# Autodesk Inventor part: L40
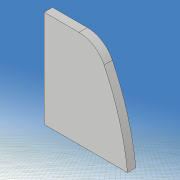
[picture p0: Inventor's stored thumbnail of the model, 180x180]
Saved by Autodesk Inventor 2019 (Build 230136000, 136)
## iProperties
Created: 2021-05
Part Number: L40
Material: 一般
Document SubType Name: Modeling
Designer: kikut
Density: 1 g/cm^3
Appearance: 既定
Mass: 0.00934248 g
Surface Area: 0.426451 cm^2
Volume: 0.00934248 cm^3
Author: kikut
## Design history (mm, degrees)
sketch "スケッチ1"
  geometry: L1 (80, 60)-(-80, 60); L2 (-80, 60)-(-80, -60); L3 (-80, -60)-(80, -60); L4 (80, -60)-(80, 60); L5 (80, 60)-(-80, -60); L6 (-80, 60)-(80, -60); 1 further point
  constraints: 12 end point, 2 midpoint, 2 parallel, 1 horizontal, 1 perpendicular
  dimensions: "d0" = 160 distance of L2.end L3.end; "d1" = 120 distance of L1.end L2.end
extrude "押し出し1" new body sketch "スケッチ1" stored distance "d2" = 0.6; taper "d3" = 0 deg
sketch "スケッチ2"
  geometry: L1 (-140, 0)-(140, 0) reference; L2 (0, -54)-(20, -30); L3 (0, 54)-(20, 30); L4 (0, -3)-(6.514, -3); L5 (6.514, -3)-(16, -6); L6 (16, -6)-(24, -3); L7 (24, -3)-(33.716, -3); L8 (0, 3)-(6.514, 3); L9 (6.514, 3)-(16, 6); L10 (16, 6)-(24, 3); L11 (24, 3)-(33.716, 3); L12 (0, -98)-(0, 98) reference; L13 (-100, -70)-(100, -70); L14 (100, -70)-(100, 70); L15 (100, 70)-(-100, 70); L16 (-100, 70)-(-100, -70); L17 (-100, -70)-(100, 70); L18 (100, -70)-(-100, 70); A1 r 60 centre (54.312, 28.5) between (0, 54) and (0, 3); A2 r 60 centre (54.312, -28.5) between (0, -3) and (0, -54); A3 r 18.111 centre (18, -12) between (20, -30) and (33.716, -3); A4 r 18.111 centre (18, 12) between (33.716, 3) and (20, 30); 1 further point
  constraints: 32 end point, 8 point on circle, 8 symmetric about line, 4 centre point, 3 horizontal, 2 collinear, 2 midpoint, 2 parallel, 1 perpendicular
  dimensions: "d5" = 60 radius of A1; "d6" = 6 distance of L8.start L4.start; "d7" = 108 distance of L3.start L2.start; "d8" = 0 horizontal distance of L3.start L8.start; "d9" = 60 distance of L3.end L2.end; "d10" = 0 horizontal distance of point (0, 0) L3.start; "d11" = 20 horizontal distance of L3.start L3.end; "d12" = 24 distance of A4.centre A3.centre; "d13" = 6 distance of L11.end L7.end; "d14" = 12 distance of L9.end L5.end; "d15" = 16 distance from line of L12 L5.end; "d16" = 24 distance from line of L6.end L12; "d17" = 200 distance of L14.end L15.end; "d18" = 140 distance of L15.end L13.start; "d30" = 18 distance from line of L12 A4.centre
extrude "押し出し2" cut sketch "スケッチ2" stored distance "d19" = 10; taper "d20" = 0 deg
sketch "スケッチ3"
  geometry: L1 (49.705, -17.97)-(33.948, -15.191); L2 (33.948, -15.191)-(34.295, -13.222); L3 (34.295, -13.222)-(50.052, -16); L4 (50.052, -16)-(49.705, -17.97); L5 (49.705, -17.97)-(34.295, -13.222); L6 (33.948, -15.191)-(50.052, -16); L7 (50.052, 16)-(34.295, 13.222); L8 (34.295, 13.222)-(33.948, 15.191); L9 (33.948, 15.191)-(49.705, 17.97); L10 (49.705, 17.97)-(50.052, 16); L11 (50.052, 16)-(33.948, 15.191); L12 (34.295, 13.222)-(49.705, 17.97); L13 (-112, 0)-(112, 0) reference; L14 (0, -84)-(0, 84) reference; 3 further points
  constraints: 24 end point, 4 midpoint, 4 parallel, 2 perpendicular, 2 symmetric about line
  dimensions: "d21" = 2 distance of L3.end L1.start; "d22" = 2 distance of L9.end L7.start; "d23" = 16 distance of L8.end L9.end; "d24" = 42 distance from line of L14 point (42, 15.596); "d26" = 10 deg angle of L7 L13; "d62" = 16 distance from line of L3.end L13
extrude "押し出し3" join sketch "スケッチ3" distance "d27" = 0.6; taper "d28" = 0 deg
fillet "フィレット1" dims "d31" = 2
fillet "フィレット2" dims "d32" = 1
sketch "スケッチ7"
  geometry: L1 (-20, 60)-(80, 60); L2 (80, 60)-(80, -60); L3 (80, -60)-(-20, -60); L4 (-20, -60)-(-20, 60); L5 (0, -82.207)-(0, 85.793) reference; L6 (-40, 0)-(100, 0) reference; L7 (30, 0)-(36, 0); L8 (36, 0)-(36, -10); L9 (36, -10)-(30, -10); L10 (30, -10)-(30, 0); 1 further point
  constraints: 16 end point, 4 parallel, 2 horizontal, 2 perpendicular, 1 other
  dimensions: "d80" = 120 distance of L3.end L1.start; "d81" = 20 distance between parallel lines of L5 L4; "d82" = 100 distance of L1.start L1.end; "d84" = 6 distance of L8.end L9.end; "d85" = 10 distance of L7.end L8.end; "d86" = 50 distance between parallel lines of L4 L10; "d93" = 50 distance between parallel lines of L3 L9
extrude "押し出し5" cut sketch "スケッチ7" stored distance "d87" = 10; taper "d88" = 0 deg
node "ソリッド1"
